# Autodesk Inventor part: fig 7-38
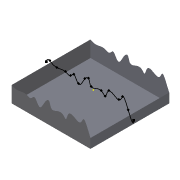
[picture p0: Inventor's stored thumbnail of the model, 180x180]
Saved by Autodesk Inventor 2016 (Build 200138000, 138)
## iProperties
Shininess: 64.0
Length Units: 11269
Angle Units: 11279
Time Units: 11290
Mass Units: 11283
Length Display Precision: 3
Angle Display Precision: 2
Compacted: True
Part Number: fig 7-38
Document SubType Name: Modeling
Created: 2002-12
Designer: deepak
Density: 1 g/cm^3
Material: Generic
Appearance: Default
Density: 0.0
Volumn: 0.0
Area: 0.0
PropertySet Name: Model Information
Control State: 0
Master: False
Checked Out: False
Author: cadcim
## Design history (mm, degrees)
sketch "Sketch1"
  geometry: L1 (-32.188, 30.089)-(27.812, 30.089); L2 (27.812, 30.089)-(27.812, -29.911); L3 (27.812, -29.911)-(-32.188, -29.911); L4 (-32.188, -29.911)-(-32.188, 30.089)
  constraints: 8 end point, 2 parallel, 1 horizontal, 1 perpendicular
  dimensions: "d0" = 60 distance of L1.start L1.end; "d1" = 60 distance of L3.end L1.start
extrude "Extrusion1" new body sketch "Sketch1" stored distance "d2" = 20; taper "d3" = 0 deg
sketch "Sketch2"
  geometry: 17 further points
  constraints: 17 other
extrude_surface "ExtrusionSrf1" sketch "Sketch2" dims "d4" = 70, "d5" = 0
split "Split1"
delete_face "Delete Face1"
node "Sketch5"
sketch "Sketch6"
  geometry: 1 further point
body "Srf1"
body "Srf2"
